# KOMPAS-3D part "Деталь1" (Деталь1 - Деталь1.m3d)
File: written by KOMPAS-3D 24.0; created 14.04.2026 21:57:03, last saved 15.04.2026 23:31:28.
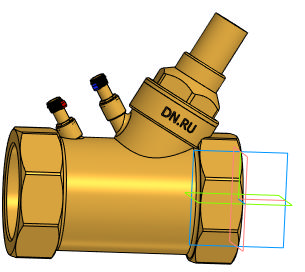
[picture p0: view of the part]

Document properties: Автор: tyuri; Полное имя файла: D:\Аутсорс\VB0000P-T Клапан балансировочный статический DN.ru\DN50\Исходные данные\Деталь1 - Деталь1.m3d

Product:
- Body: Твердое тело1  | qty 1
    Масса: 2.22336
- Part/product: Деталь1
    Масса: 2.22336
    additional columns: Типовые

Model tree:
1. Твердое тело1  (labels: Твердое тело1)
2. Эскиз:1  (labels: Грань.Твердое тело1)
3. Элемент выдавливания:2  (labels: Грань.Твердое тело1)
     Расстояние 2 = -43.4162
4. Изменить положение граней:1  (labels: Грань.Твердое тело1)
     Расстояние = 2.5
5. Изменить положение граней:2  (labels: Грань.Твердое тело1)
     Расстояние = 2.5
